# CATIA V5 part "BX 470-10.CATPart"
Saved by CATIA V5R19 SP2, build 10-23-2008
Part number: BX 470-10
Bounding box of the stored display mesh (mm): x -37.351 to 37.351, y -37.351 to 37.351, z 0 to 80
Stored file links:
  C:\Users\Bora\Desktop\3D Katı model\BX serisi\BX 470\BX 470-10.CATPart
  C:\Program Files\Dassault Systemes\B19\intel_a\reffiles\standard\MetricThickPitch.txt
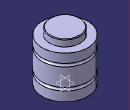
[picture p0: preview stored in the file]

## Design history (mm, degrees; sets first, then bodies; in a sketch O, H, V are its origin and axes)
Body1 (main body)
  Sketch1 on yz-plane, origin (0, 0, 0), H (0, 1, 0), V (0, 0, 1)
    point P2 (37.5, 15.5)
    line L1 (37.5, 15.5) -> (37.5, 0)
    point P3 (37.5, 20.5)
    point P4 (37.5, 49.5)
    line L2 (37.5, 49.5) -> (37.5, 20.5)
    point P6 (25, 79)
    arc A1 centre (24, 79) radius 1 from (25, 79) to (24, 80) ccw
    point P8 (25, 79)
    line L3 (25, 79) -> (25, 69)
    point P9 (37.5, 54.5)
    line L4 (37.5, 69) -> (37.5, 54.5)
    point P11 (37.5, 15.5)
    point P12 (37.5, 20.5)
    arc A2 centre (37.5, 18) radius 2.5 from (37.5, 20.5) to (37.5, 15.5) ccw
    point P13 (37.5, 49.5)
    point P14 (37.5, 54.5)
    arc A3 centre (37.5, 52) radius 2.5 from (37.5, 54.5) to (37.5, 49.5) ccw
    line L5 (24, 80) -> (0, 80)
    line L6 (25, 69) -> (37.5, 69)
    line L7 (37.5, 0) -> (0, 0)
    horizontal: L5 H, L6 H, L7 H
    coincidence: P2 P11, P3 P12, P4 P13, P6 P8, P9 P14
  Shaft1: profile Sketch1, axis Sketch1.V, angle 360
  Sketch2 on face of Shaft1 from Sketch1.L7, origin (0, 0, 0), H (1, 0, 0), V (0, -1, 0)
    point P1 (20, 0)
    distance P1 V = 20
  Hole1: placed by Sketch2, at (20, 0, 0) direction (0, 0, 1), diameter 6.647, depth 7, threaded "M8", thread diameter 8, thread depth 7, pitch 1.25
  CircPattern1: of Hole1, instances 4, angular step 90 {= 360.0*1 deg/CircPattern1.AngularNumber}, axis from xy-plane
